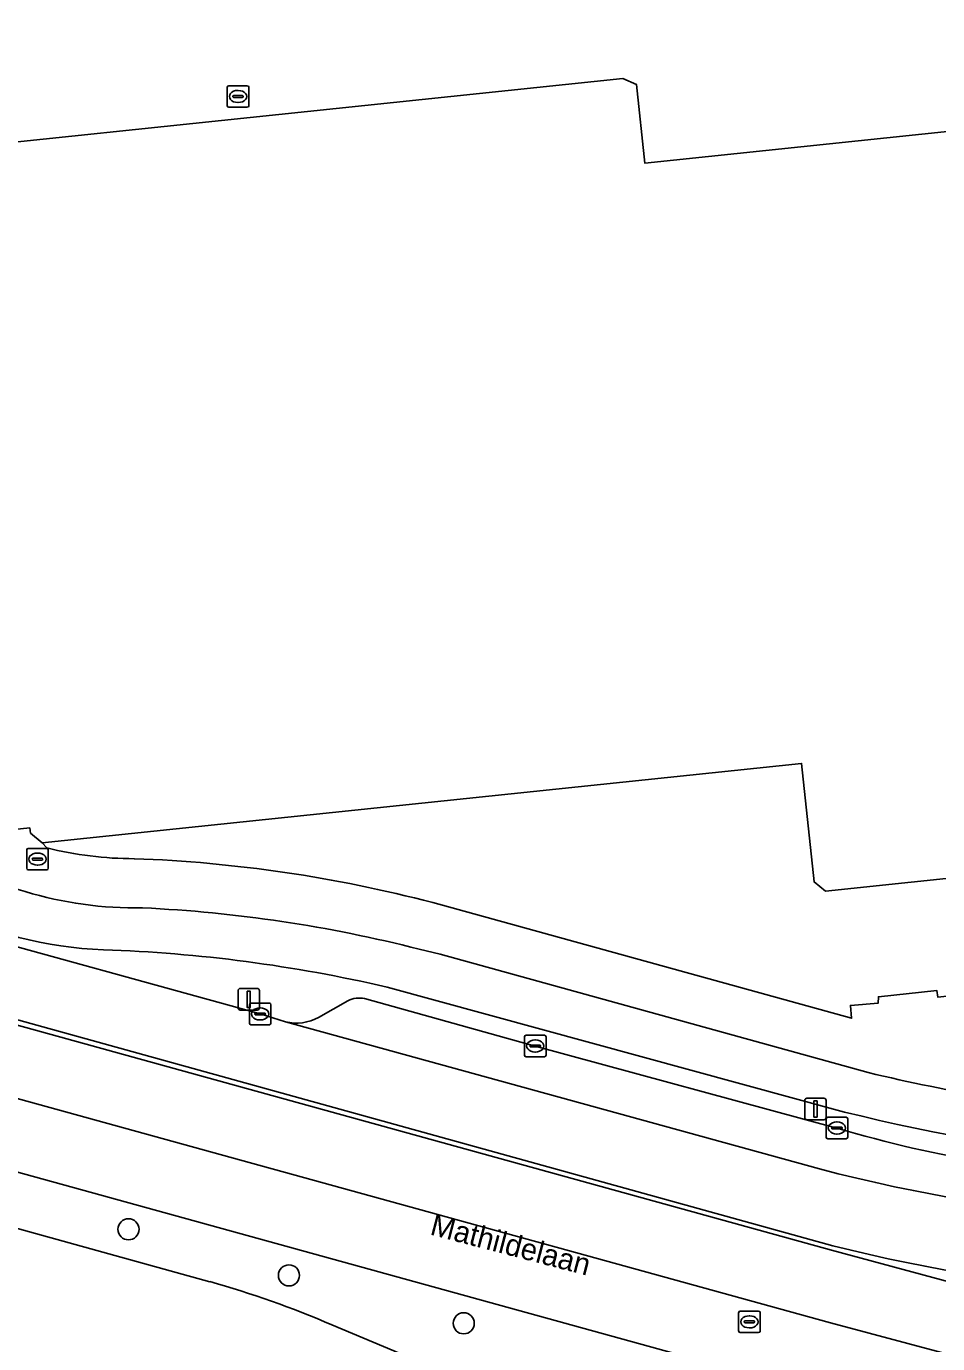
# Model space of a CAD drawing. Extents: x 160675 to 161153, y 383241 to 383714.
# Drawn here: x 160904.8 to 160947.1, y 383561.6 to 383622.7 of the extents above; entities that cross this region are included whole.
import ezdxf

# ---------------------------------------------------------------- set-up
doc = ezdxf.new("R2010")
doc.units = 0
for name, color, linetype in [('IMGEO_Berm_groen', 7, 'Continuous'), ('IMGEO_Berm_open', 7, 'Continuous'), ('IMGEO_Boom', 7, 'Continuous'), ('IMGEO_Erf', 7, 'Continuous'), ('IMGEO_Fietspad_gesloten', 7, 'Continuous'), ('IMGEO_Groenvoorziening', 7, 'Continuous'), ('IMGEO_Kolk', 7, 'Continuous'), ('IMGEO_Lichtmast', 7, 'Continuous'), ('IMGEO_Openbare_ruimte_label', 7, 'Continuous'), ('IMGEO_OVBaan_gesloten', 7, 'Continuous'), ('IMGEO_Pand', 7, 'Continuous'), ('IMGEO_Parkeervlak_open', 7, 'Continuous'), ('IMGEO_Rijbaan_lokaal_gesloten', 7, 'Continuous'), ('IMGEO_Rioolput', 7, 'Continuous'), ('IMGEO_Voetpad_open', 7, 'Continuous')]:
    doc.layers.add(name, color=color, linetype=linetype)

msp = doc.modelspace()

# ---------------------------------------------------------------- linework, layer by layer
at = {"layer": 'IMGEO_Berm_groen'}
for points in [[(160870.684, 383578.867), (160797.835, 383598.49), (160797.171, 383596.125), (160869.874, 383576.512), (160913.282, 383564.496)], [(160946.568, 383557.927), (160870.684, 383578.867)], [(160918.949, 383562.487), (160924.508, 383560.159), (160928.246, 383558.692), (160936.421, 383556.028)]]:
    msp.add_lwpolyline(points, dxfattribs=at)
msp.add_arc((160901.399, 383521.98), 44.146, 66.57534, 74.38495, dxfattribs=at)
at = {"layer": 'IMGEO_Berm_open'}
for points in [[(160942.181, 383566.161), (160883.368, 383582.463), (160880.432, 383583.23), (160880.388, 383583.018), (160942.127, 383565.955), (160949.177, 383564.05)], [(160900.702, 383581.864), (160900.478, 383581.054), (160900.672, 383581.034), (160915.614, 383576.913), (160916.793, 383576.556)], [(160942.723, 383572.366), (160921.511, 383578.159)], [(160918.327, 383576.756), (160919.688, 383577.526)], [(160920.462, 383577.626), (160928.377, 383575.427), (160942.374, 383571.622)]]:
    msp.add_lwpolyline(points, dxfattribs=at)
for centre, radius, start, end in [((160909.053, 383598.434), 18.555, 243.25209, 267.81276), ((160906.022, 383511.365), 68.566, 76.94433, 88.05856), ((160920.215, 383576.493), 1.16, 77.70508, 117.01847), ((160917.31, 383578.57), 2.079, 255.59059, 299.26583), ((160961.872, 383648.668), 78.668, 255.91174, 275.49255), ((160958.774, 383626.604), 57.376, 253.39085, 267.89005), ((160961.248, 383641.837), 78.041, 255.85815, 276.46401)]:
    msp.add_arc(centre, radius, start, end, dxfattribs=at)
at = {"layer": 'IMGEO_Boom'}
for centre in [(160909.509, 383566.926), (160916.953, 383564.787), (160925.064, 383562.565)]:
    msp.add_circle(centre, 0.489, dxfattribs=at)
at = {"layer": 'IMGEO_Erf'}
msp.add_lwpolyline([(160866.054, 383633.173), (160867.696, 383617.451), (160865.631, 383617.236), (160866.271, 383611.111), (160870.187, 383611.394), (160875.353, 383611.813), (160876.361, 383611.895), (160881.571, 383612.317), (160884.121, 383612.524), (160883.882, 383614.811), (160884.254, 383615.27), (160932.445, 383620.304), (160933.08, 383620.021), (160933.46, 383616.382), (160974.675, 383620.687), (160975.232, 383620.235), (160975.885, 383613.983), (160978.737, 383614.28), (160979.633, 383613.553), (160980.78, 383613.583), (160979.179, 383629.584)], dxfattribs=at)
at = {"layer": 'IMGEO_Fietspad_gesloten'}
for points in [[(160943.827, 383574.197), (160923.962, 383579.682), (160922.998, 383579.919)], [(160921.511, 383578.159), (160942.723, 383572.366)]]:
    msp.add_lwpolyline(points, dxfattribs=at)
for centre, radius, start, end in [((160909.843, 383599.533), 17.7, 235.3181, 271.04589), ((160909.053, 383598.434), 18.555, 243.25209, 267.81276), ((160907.181, 383517.913), 63.992, 75.68938, 87.32596), ((160906.022, 383511.365), 68.566, 76.94433, 88.05856), ((160961.787, 383648.532), 76.474, 256.41726, 265.25743), ((160961.872, 383648.668), 78.668, 255.91174, 275.49255)]:
    msp.add_arc(centre, radius, start, end, dxfattribs=at)
at = {"layer": 'IMGEO_Groenvoorziening'}
msp.add_lwpolyline([(160923.625, 383582.077), (160943.059, 383576.719), (160943.007, 383577.314), (160944.295, 383577.422), (160944.303, 383577.711), (160947.02, 383577.997), (160947.052, 383577.699), (160950.193, 383578.027), (160950.172, 383578.233), (160953.077, 383578.527), (160953.051, 383578.774), (160954.349, 383578.909), (160954.216, 383580.184), (160954.439, 383580.207), (160954.067, 383583.889), (160941.844, 383582.612), (160941.315, 383583.041), (160940.741, 383588.532), (160905.51, 383584.853), (160905.714, 383584.622)], dxfattribs=at)
for centre, radius, start, end in [((160909.768, 383600.638), 16.521, 255.79701, 270.04315), ((160907.489, 383520.569), 63.589, 75.30049, 87.93557)]:
    msp.add_arc(centre, radius, start, end, dxfattribs=at)
at = {"layer": 'IMGEO_Kolk'}
for p, q in [((160915.192, 383577.414), (160916.044, 383577.414)), ((160915.117, 383576.488), (160915.117, 383577.34)), ((160915.376, 383576.908), (160915.376, 383576.92)), ((160915.814, 383576.871), (160915.416, 383576.871)), ((160915.419, 383576.957), (160915.817, 383576.957)), ((160915.605, 383577.194), (160915.63, 383577.194)), ((160915.86, 383576.92), (160915.86, 383576.908)), ((160916.118, 383577.34), (160916.118, 383576.488)), ((160916.044, 383576.414), (160915.192, 383576.414)), ((160915.628, 383576.634), (160915.603, 383576.634)), ((160927.88, 383575.002), (160927.88, 383575.854)), ((160927.955, 383575.928), (160928.807, 383575.928)), ((160928.368, 383575.708), (160928.393, 383575.708)), ((160928.881, 383575.854), (160928.881, 383575.002)), ((160928.807, 383574.928), (160927.955, 383574.928)), ((160928.139, 383575.422), (160928.139, 383575.434)), ((160928.577, 383575.385), (160928.179, 383575.385)), ((160928.182, 383575.471), (160928.58, 383575.471)), ((160928.391, 383575.148), (160928.366, 383575.148)), ((160928.623, 383575.434), (160928.623, 383575.422)), ((160941.877, 383571.198), (160941.877, 383572.05)), ((160941.952, 383572.124), (160942.804, 383572.124)), ((160942.365, 383571.904), (160942.39, 383571.904)), ((160942.878, 383572.05), (160942.878, 383571.198)), ((160942.136, 383571.618), (160942.136, 383571.63)), ((160942.574, 383571.581), (160942.176, 383571.581)), ((160942.179, 383571.667), (160942.577, 383571.667)), ((160942.388, 383571.344), (160942.363, 383571.344)), ((160942.62, 383571.63), (160942.62, 383571.618)), ((160942.804, 383571.124), (160941.952, 383571.124))]:
    msp.add_line(p, q, dxfattribs=at)
for points in [[(160915.192, 383577.414), (160916.044, 383577.414)], [(160915.117, 383576.488), (160915.117, 383577.34)], [(160916.118, 383577.34), (160916.118, 383576.488)], [(160916.044, 383576.414), (160915.192, 383576.414)], [(160927.88, 383575.002), (160927.88, 383575.854)], [(160927.955, 383575.928), (160928.807, 383575.928)], [(160928.881, 383575.854), (160928.881, 383575.002)], [(160928.807, 383574.928), (160927.955, 383574.928)], [(160941.877, 383571.198), (160941.877, 383572.05)], [(160941.952, 383572.124), (160942.804, 383572.124)], [(160942.878, 383572.05), (160942.878, 383571.198)], [(160942.804, 383571.124), (160941.952, 383571.124)]]:
    msp.add_lwpolyline(points, dxfattribs=at)
for centre, radius, start, end in [((160915.194, 383577.338), 0.0765, 91.55205, 178.44795), ((160915.194, 383577.338), 0.0765, 91.55205, 178.44795), ((160916.042, 383577.338), 0.0765, 1.55205, 88.44795), ((160916.042, 383577.338), 0.0765, 1.55205, 88.44795), ((160915.416, 383576.917), 0.0403, 85.87752, 175.75265), ((160915.413, 383576.907), 0.0366, 178.93798, 274.71019), ((160915.817, 383576.914), 0.043, 264.86636, 352.45326), ((160915.821, 383576.919), 0.0386, 1.73085, 96.63898), ((160915.194, 383576.49), 0.0765, 181.55205, 268.44795), ((160915.194, 383576.49), 0.0765, 181.55205, 268.44795), ((160916.042, 383576.49), 0.0765, 271.55205, 358.44795), ((160916.042, 383576.49), 0.0765, 271.55205, 358.44795), ((160927.957, 383575.852), 0.0765, 91.55205, 178.44795), ((160927.957, 383575.852), 0.0765, 91.55205, 178.44795), ((160928.805, 383575.852), 0.0765, 1.55205, 88.44795), ((160928.805, 383575.852), 0.0765, 1.55205, 88.44795), ((160927.957, 383575.004), 0.0765, 181.55205, 268.44795), ((160927.957, 383575.004), 0.0765, 181.55205, 268.44795), ((160928.179, 383575.431), 0.0403, 85.87752, 175.75265), ((160928.176, 383575.421), 0.0366, 178.93798, 274.71019), ((160928.58, 383575.428), 0.043, 264.86636, 352.45326), ((160928.584, 383575.433), 0.0386, 1.73085, 96.63898), ((160928.805, 383575.004), 0.0765, 271.55205, 358.44795), ((160928.805, 383575.004), 0.0765, 271.55205, 358.44795), ((160941.954, 383572.048), 0.0765, 91.55205, 178.44795), ((160941.954, 383572.048), 0.0765, 91.55205, 178.44795), ((160942.802, 383572.048), 0.0765, 1.55205, 88.44795), ((160942.802, 383572.048), 0.0765, 1.55205, 88.44795), ((160942.176, 383571.627), 0.0403, 85.87752, 175.75265), ((160942.173, 383571.617), 0.0366, 178.93798, 274.71019), ((160942.577, 383571.624), 0.043, 264.86636, 352.45326), ((160942.581, 383571.629), 0.0386, 1.73085, 96.63898), ((160941.954, 383571.2), 0.0765, 181.55205, 268.44795), ((160941.954, 383571.2), 0.0765, 181.55205, 268.44795), ((160942.802, 383571.2), 0.0765, 271.55205, 358.44795), ((160942.802, 383571.2), 0.0765, 271.55205, 358.44795)]:
    msp.add_arc(centre, radius, start, end, dxfattribs=at)
for centre, major_axis, ratio, start_param, end_param in [((160915.604, 383576.914), (-0.387, 0.002), 0.722429, 4.712389, 7.853982), ((160915.629, 383576.914), (-0.39, 0.002), 0.717154, 1.570796, 4.712389), ((160928.367, 383575.428), (-0.387, 0.002), 0.722429, 4.712389, 7.853982), ((160928.392, 383575.428), (-0.39, 0.002), 0.717154, 1.570796, 4.712389), ((160942.364, 383571.624), (-0.387, 0.002), 0.722429, 4.712389, 7.853982), ((160942.389, 383571.624), (-0.39, 0.002), 0.717154, 1.570796, 4.712389)]:
    msp.add_ellipse(centre, major_axis=major_axis, ratio=ratio, start_param=start_param, end_param=end_param, dxfattribs=at)
at = {"layer": 'IMGEO_Lichtmast'}
for p, q in [((160914.592, 383577.196), (160914.592, 383577.996)), ((160914.592, 383577.996), (160914.592, 383577.196)), ((160914.692, 383578.096), (160915.482, 383578.096)), ((160915.482, 383578.096), (160914.692, 383578.096)), ((160915.582, 383577.996), (160915.582, 383577.196)), ((160915.582, 383577.196), (160915.582, 383577.996)), ((160915.482, 383577.096), (160914.692, 383577.096)), ((160914.692, 383577.096), (160915.482, 383577.096)), ((160940.887, 383572.104), (160940.887, 383572.904)), ((160940.887, 383572.904), (160940.887, 383572.104)), ((160940.987, 383573.004), (160941.777, 383573.004)), ((160941.777, 383573.004), (160940.987, 383573.004)), ((160941.877, 383572.904), (160941.877, 383572.104)), ((160941.877, 383572.104), (160941.877, 383572.904)), ((160941.777, 383572.004), (160940.987, 383572.004)), ((160940.987, 383572.004), (160941.777, 383572.004))]:
    msp.add_line(p, q, dxfattribs=at)
for points in [[(160915.012, 383577.971), (160915.162, 383577.971), (160915.162, 383577.221), (160915.012, 383577.221), (160915.012, 383577.971)], [(160941.307, 383572.879), (160941.457, 383572.879), (160941.457, 383572.129), (160941.307, 383572.129), (160941.307, 383572.879)]]:
    msp.add_lwpolyline(points, dxfattribs=at)
for centre, start, end in [((160914.692, 383577.996), 90, 180), ((160914.692, 383577.996), 90, 180), ((160915.482, 383577.996), 0, 90), ((160915.482, 383577.996), 360, 90), ((160914.692, 383577.196), 180, 270), ((160914.692, 383577.196), 180, 270), ((160915.482, 383577.196), 270, 0), ((160915.482, 383577.196), 270, 0), ((160940.987, 383572.904), 90, 180), ((160940.987, 383572.904), 90, 180), ((160941.777, 383572.904), 0, 90), ((160941.777, 383572.904), 360, 90), ((160940.987, 383572.104), 180, 270), ((160940.987, 383572.104), 180, 270), ((160941.777, 383572.104), 270, 0), ((160941.777, 383572.104), 270, 0)]:
    msp.add_arc(centre, 0.1, start, end, dxfattribs=at)
at = {"layer": 'IMGEO_OVBaan_gesloten'}
for points in [[(160760.567, 383616.024), (160759.368, 383616.453), (160756.884, 383613.99), (160761.763, 383612.059), (160766.781, 383610.37), (160770.415, 383609.332), (160774.938, 383608.123), (160890.249, 383576.873), (160942.076, 383562.592), (160950.815, 383560.255), (160956.785, 383559.216), (160962.841, 383558.697), (160968.725, 383558.524), (160975.387, 383558.61), (160977.148, 383558.794), (160977.505, 383562.304), (160973.835, 383561.901)], [(160973.434, 383555.262), (160976.812, 383555.49), (160977.148, 383558.794), (160975.387, 383558.61), (160968.725, 383558.524), (160962.841, 383558.697), (160956.785, 383559.216), (160950.815, 383560.255), (160942.076, 383562.592), (160890.249, 383576.873), (160774.938, 383608.123), (160770.415, 383609.332), (160766.781, 383610.37), (160761.763, 383612.059), (160756.884, 383613.99)], [(160949.177, 383564.05), (160942.127, 383565.955), (160880.388, 383583.018), (160880.346, 383582.924), (160861.613, 383588.006), (160783.094, 383609.33)], [(160765.95, 383607.15), (160797.835, 383598.49), (160870.684, 383578.867), (160946.568, 383557.927)]]:
    msp.add_lwpolyline(points, dxfattribs=at)
at = {"layer": 'IMGEO_Pand'}
for points in [[(160974.675, 383620.687), (160933.46, 383616.382), (160933.08, 383620.021), (160932.445, 383620.304), (160884.254, 383615.27)], [(160902.182, 383585.26), (160904.93, 383585.547), (160904.956, 383585.302), (160905.51, 383584.853), (160940.741, 383588.532), (160941.315, 383583.041), (160941.844, 383582.612), (160954.067, 383583.889)]]:
    msp.add_lwpolyline(points, dxfattribs=at)
at = {"layer": 'IMGEO_Parkeervlak_open'}
for points in [[(160919.688, 383577.526), (160918.327, 383576.756)], [(160942.374, 383571.622), (160928.377, 383575.427), (160920.462, 383577.626)], [(160916.793, 383576.556), (160941.567, 383569.725)]]:
    msp.add_lwpolyline(points, dxfattribs=at)
for centre, radius, start, end in [((160920.215, 383576.493), 1.16, 77.70508, 117.01847), ((160917.31, 383578.57), 2.079, 255.59059, 299.26583), ((160958.774, 383626.604), 57.376, 253.39085, 267.89005), ((160961.705, 383647.262), 80.11, 255.44106, 275.88609)]:
    msp.add_arc(centre, radius, start, end, dxfattribs=at)
at = {"layer": 'IMGEO_Rijbaan_lokaal_gesloten'}
for points in [[(160784.127, 383609.308), (160809.68, 383602.419), (160845.226, 383592.848), (160861.742, 383588.359), (160861.613, 383588.006), (160880.346, 383582.924), (160880.388, 383583.018), (160880.432, 383583.23), (160883.368, 383582.463), (160942.181, 383566.161)], [(160941.567, 383569.725), (160916.793, 383576.556), (160915.614, 383576.913), (160900.672, 383581.034), (160900.478, 383581.054), (160885.78, 383585.094), (160883.615, 383585.679), (160860.267, 383592.107), (160853.258, 383594.012), (160833.46, 383599.346), (160823.497, 383602.007)], [(160913.282, 383564.496), (160869.874, 383576.512)], [(160936.421, 383556.028), (160928.246, 383558.692), (160924.508, 383560.159), (160918.949, 383562.487)]]:
    msp.add_lwpolyline(points, dxfattribs=at)
for centre, radius, start, end in [((160961.705, 383647.262), 80.11, 255.44106, 275.88609), ((160961.248, 383641.837), 78.041, 255.85815, 276.46401), ((160901.399, 383521.98), 44.146, 66.57534, 74.38495)]:
    msp.add_arc(centre, radius, start, end, dxfattribs=at)
at = {"layer": 'IMGEO_Rioolput'}
for p, q in [((160914.091, 383619.046), (160914.091, 383619.898)), ((160914.166, 383619.972), (160915.018, 383619.972)), ((160914.579, 383619.752), (160914.604, 383619.752)), ((160915.092, 383619.898), (160915.092, 383619.046)), ((160915.018, 383618.972), (160914.166, 383618.972)), ((160914.35, 383619.466), (160914.35, 383619.478)), ((160914.788, 383619.429), (160914.39, 383619.429)), ((160914.393, 383619.515), (160914.791, 383619.515)), ((160914.602, 383619.192), (160914.577, 383619.192)), ((160914.834, 383619.478), (160914.834, 383619.466)), ((160904.787, 383583.67), (160904.787, 383584.522)), ((160904.862, 383584.596), (160905.714, 383584.596)), ((160905.046, 383584.09), (160905.046, 383584.102)), ((160905.089, 383584.139), (160905.487, 383584.139)), ((160905.275, 383584.376), (160905.3, 383584.376)), ((160905.53, 383584.102), (160905.53, 383584.09)), ((160905.788, 383584.522), (160905.788, 383583.67)), ((160905.714, 383583.596), (160904.862, 383583.596)), ((160905.484, 383584.053), (160905.086, 383584.053)), ((160905.298, 383583.816), (160905.273, 383583.816)), ((160937.818, 383562.207), (160937.818, 383563.059)), ((160937.893, 383563.133), (160938.745, 383563.133)), ((160938.306, 383562.913), (160938.331, 383562.913)), ((160938.819, 383563.059), (160938.819, 383562.207)), ((160938.745, 383562.133), (160937.893, 383562.133)), ((160938.077, 383562.627), (160938.077, 383562.639)), ((160938.515, 383562.59), (160938.117, 383562.59)), ((160938.12, 383562.676), (160938.518, 383562.676)), ((160938.329, 383562.353), (160938.304, 383562.353)), ((160938.561, 383562.639), (160938.561, 383562.627))]:
    msp.add_line(p, q, dxfattribs=at)
for points in [[(160914.091, 383619.046), (160914.091, 383619.898)], [(160914.166, 383619.972), (160915.018, 383619.972)], [(160915.092, 383619.898), (160915.092, 383619.046)], [(160915.018, 383618.972), (160914.166, 383618.972)], [(160904.787, 383583.67), (160904.787, 383584.522)], [(160904.862, 383584.596), (160905.714, 383584.596)], [(160905.788, 383584.522), (160905.788, 383583.67)], [(160905.714, 383583.596), (160904.862, 383583.596)], [(160937.818, 383562.207), (160937.818, 383563.059)], [(160937.893, 383563.133), (160938.745, 383563.133)], [(160938.819, 383563.059), (160938.819, 383562.207)], [(160938.745, 383562.133), (160937.893, 383562.133)]]:
    msp.add_lwpolyline(points, dxfattribs=at)
for centre, radius, start, end in [((160914.168, 383619.896), 0.0765, 91.55205, 178.44795), ((160914.168, 383619.896), 0.0765, 91.55205, 178.44795), ((160915.016, 383619.896), 0.0765, 1.55205, 88.44795), ((160915.016, 383619.896), 0.0765, 1.55205, 88.44795), ((160914.168, 383619.048), 0.0765, 181.55205, 268.44795), ((160914.168, 383619.048), 0.0765, 181.55205, 268.44795), ((160914.39, 383619.475), 0.0403, 85.87752, 175.75265), ((160914.387, 383619.465), 0.0366, 178.93798, 274.71019), ((160914.791, 383619.472), 0.043, 264.86636, 352.45326), ((160914.795, 383619.477), 0.0386, 1.73085, 96.63898), ((160915.016, 383619.048), 0.0765, 271.55205, 358.44795), ((160915.016, 383619.048), 0.0765, 271.55205, 358.44795), ((160904.864, 383584.52), 0.0765, 91.55205, 178.44795), ((160904.864, 383584.52), 0.0765, 91.55205, 178.44795), ((160905.086, 383584.099), 0.0403, 85.87752, 175.75265), ((160905.083, 383584.089), 0.0366, 178.93798, 274.71019), ((160905.487, 383584.096), 0.043, 264.86636, 352.45326), ((160905.491, 383584.101), 0.0386, 1.73085, 96.63898), ((160905.712, 383584.52), 0.0765, 1.55205, 88.44795), ((160905.712, 383584.52), 0.0765, 1.55205, 88.44795), ((160904.864, 383583.672), 0.0765, 181.55205, 268.44795), ((160904.864, 383583.672), 0.0765, 181.55205, 268.44795), ((160905.712, 383583.672), 0.0765, 271.55205, 358.44795), ((160905.712, 383583.672), 0.0765, 271.55205, 358.44795), ((160937.895, 383563.057), 0.0765, 91.55205, 178.44795), ((160937.895, 383563.057), 0.0765, 91.55205, 178.44795), ((160938.743, 383563.057), 0.0765, 1.55205, 88.44795), ((160938.743, 383563.057), 0.0765, 1.55205, 88.44795), ((160937.895, 383562.209), 0.0765, 181.55205, 268.44795), ((160937.895, 383562.209), 0.0765, 181.55205, 268.44795), ((160938.117, 383562.636), 0.0403, 85.87752, 175.75265), ((160938.114, 383562.626), 0.0366, 178.93798, 274.71019), ((160938.518, 383562.633), 0.043, 264.86636, 352.45326), ((160938.522, 383562.638), 0.0386, 1.73085, 96.63898), ((160938.743, 383562.209), 0.0765, 271.55205, 358.44795), ((160938.743, 383562.209), 0.0765, 271.55205, 358.44795)]:
    msp.add_arc(centre, radius, start, end, dxfattribs=at)
for centre, major_axis, ratio, start_param, end_param in [((160914.578, 383619.472), (-0.387, 0.002), 0.722429, 4.712389, 7.853982), ((160914.603, 383619.472), (-0.39, 0.002), 0.717154, 1.570796, 4.712389), ((160905.274, 383584.096), (-0.387, 0.002), 0.722429, 4.712389, 7.853982), ((160905.299, 383584.096), (-0.39, 0.002), 0.717154, 1.570796, 4.712389), ((160938.305, 383562.633), (-0.387, 0.002), 0.722429, 4.712389, 7.853982), ((160938.33, 383562.633), (-0.39, 0.002), 0.717154, 1.570796, 4.712389)]:
    msp.add_ellipse(centre, major_axis=major_axis, ratio=ratio, start_param=start_param, end_param=end_param, dxfattribs=at)
at = {"layer": 'IMGEO_Voetpad_open'}
for points in [[(160905.714, 383584.622), (160905.51, 383584.853), (160904.956, 383585.302), (160904.93, 383585.547), (160902.182, 383585.26), (160901.27, 383586), (160900.768, 383590.806), (160897.942, 383590.511), (160893.519, 383590.049), (160892.87, 383590.575), (160892.793, 383591.317)], [(160947.052, 383577.699), (160947.02, 383577.997), (160944.303, 383577.711), (160944.295, 383577.422), (160943.007, 383577.314), (160943.059, 383576.719), (160923.625, 383582.077)], [(160922.998, 383579.919), (160923.962, 383579.682), (160943.827, 383574.197)]]:
    msp.add_lwpolyline(points, dxfattribs=at)
for centre, radius, start, end in [((160909.843, 383599.533), 17.7, 235.3181, 271.04589), ((160909.768, 383600.638), 16.521, 255.79701, 270.04315), ((160907.489, 383520.569), 63.589, 75.30049, 87.93557), ((160907.181, 383517.913), 63.992, 75.68938, 87.32596), ((160961.787, 383648.532), 76.474, 256.41726, 265.25743)]:
    msp.add_arc(centre, radius, start, end, dxfattribs=at)

# ---------------------------------------------------------------- texts
at = {"layer": 'IMGEO_Openbare_ruimte_label'}
msp.add_text('Mathildelaan', height=1, rotation=345.33813, dxfattribs=at).set_placement((160923.453, 383566.692))

doc.saveas('drawing.dxf')
